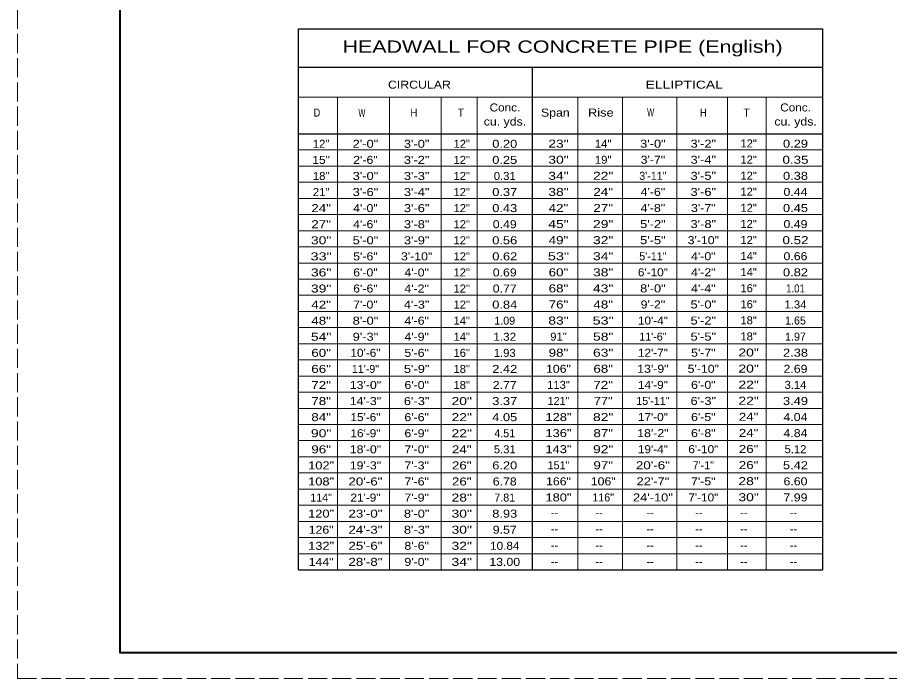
# Model space of a CAD drawing. Extents: x 685.4 to 719.4, y 1059.8 to 1105.8.
# Drawn here: x 685.44 to 702.44, y 1059.77 to 1072.65 of the extents above; entities that cross this region are included whole.
import ezdxf
from ezdxf.enums import TextEntityAlignment as Align

# ---------------------------------------------------------------- set-up
doc = ezdxf.new("R2010")
doc.units = 0
doc.header["$LTSCALE"] = 0.062
doc.linetypes.add('LONG_DASHED', pattern=[7.5, 6, -1.5])
doc.layers.add('1', color=7, linetype='Continuous', lineweight=13)

msp = doc.modelspace()

# ---------------------------------------------------------------- linework, layer by layer
at = {"layer": '1', "lineweight": 25}
for p, q in [((690.91875, 1061.88917), (690.91875, 1072.433)), ((690.91875, 1072.433), (701.14175, 1072.433)), ((701.14175, 1061.88917), (701.14175, 1072.433)), ((690.91875, 1071.68142), (701.14175, 1071.68142)), ((695.4815, 1061.88917), (695.4815, 1071.68142)), ((690.91875, 1070.38517), (701.14175, 1070.38517)), ((690.91875, 1061.88917), (701.14175, 1061.88917))]:
    msp.add_line(p, q, dxfattribs=at)
at = {"layer": '1'}
for p, q in [((690.91875, 1071.10025), (701.14175, 1071.10025)), ((691.6805, 1061.88917), (691.6805, 1071.10025)), ((692.69092, 1061.88917), (692.69092, 1071.10025)), ((693.70033, 1061.88917), (693.70033, 1071.10025)), ((694.40242, 1061.88917), (694.40242, 1071.10025)), ((696.36608, 1061.88917), (696.36608, 1071.10025)), ((697.23733, 1061.88917), (697.23733, 1071.10025)), ((698.29567, 1061.88917), (698.29567, 1071.10025)), ((699.2805, 1061.88917), (699.2805, 1071.10025)), ((700.03325, 1061.88917), (700.03325, 1071.10025)), ((690.91875, 1070.0705), (701.14175, 1070.0705)), ((690.91875, 1069.75583), (701.14175, 1069.75583)), ((690.91875, 1069.44117), (701.14175, 1069.44117)), ((690.91875, 1069.1265), (701.14175, 1069.1265)), ((690.91875, 1068.81183), (701.14175, 1068.81183)), ((690.91875, 1068.49717), (701.14175, 1068.49717)), ((690.91875, 1068.1825), (701.14175, 1068.1825)), ((690.91875, 1067.86783), (701.14175, 1067.86783)), ((690.91875, 1067.55317), (701.14175, 1067.55317)), ((690.91875, 1067.2385), (701.14175, 1067.2385)), ((690.91875, 1066.92383), (701.14175, 1066.92383)), ((690.91875, 1066.60917), (701.14175, 1066.60917)), ((690.91875, 1066.2945), (701.14175, 1066.2945)), ((690.91875, 1065.97983), (701.14175, 1065.97983)), ((690.91875, 1065.66517), (701.14175, 1065.66517)), ((690.91875, 1065.3505), (701.14175, 1065.3505)), ((690.91875, 1065.03583), (701.14175, 1065.03583)), ((690.91875, 1064.72117), (701.14175, 1064.72117)), ((690.91875, 1064.4065), (701.14175, 1064.4065)), ((690.91875, 1064.09183), (701.14175, 1064.09183)), ((690.91875, 1063.77717), (701.14175, 1063.77717)), ((690.91875, 1063.4625), (701.14175, 1063.4625)), ((690.91875, 1063.14783), (701.14175, 1063.14783)), ((690.91875, 1062.83317), (701.14175, 1062.83317)), ((690.91875, 1062.5185), (701.14175, 1062.5185)), ((690.91875, 1062.20383), (701.14175, 1062.20383))]:
    msp.add_line(p, q, dxfattribs=at)
at = {"layer": '1', "linetype": 'LONG_DASHED'}
msp.add_lwpolyline([(685.44108, 1059.77067), (719.44108, 1059.77067), (719.44108, 1081.77067), (685.44108, 1081.77067)], close=True, dxfattribs=at)
at = {"layer": '1', "lineweight": 25}
msp.add_lwpolyline([(718.94108, 1060.27067), (687.44108, 1060.27067), (687.44108, 1081.27067)], dxfattribs=at)
at = {"layer": '1', "lineweight": 40}
msp.add_lwpolyline([(687.44108, 1081.27067), (718.94108, 1081.27067), (718.94108, 1060.27067), (687.44108, 1060.27067)], close=True, dxfattribs=at)

# ---------------------------------------------------------------- texts
at = {"layer": '1'}
for s, height, width, p in [('HEADWALL FOR CONCRETE PIPE (English)', 0.24, 1.3, (691.77833, 1071.96442)), ('CIRCULAR', 0.156, 1.15, (692.66392, 1071.2655)), ('ELLIPTICAL', 0.156, 1.3, (697.68483, 1071.2655)), ('D', 0.156, 0.85, (691.216, 1070.72058)), ('W', 0.156, 0.7, (692.08658, 1070.71608)), ('H', 0.156, 0.9, (693.10075, 1070.72275)), ('Span', 0.156, 1.15, (695.646, 1070.72058)), ('Rise', 0.156, 1.2, (696.5625, 1070.72108)), ('W', 0.156, 0.7, (697.71475, 1070.72442)), ('H', 0.156, 0.9, (698.74292, 1070.72108))]:
    msp.add_text(s, height=height, dxfattribs=dict(at, width=width)).set_placement(p)
for s, height, p in [('T', 0.156, (694.0215, 1070.72108)), ('T', 0.156, (699.59017, 1070.72275)), ('--', 0.16, (695.841, 1062.922)), ('--', 0.16, (696.70675, 1062.922)), ('--', 0.16, (697.70033, 1062.922)), ('--', 0.16, (698.65133, 1062.922)), ('--', 0.16, (699.53133, 1062.922)), ('--', 0.16, (700.4965, 1062.922)), ('--', 0.16, (695.841, 1062.60467)), ('--', 0.16, (696.70675, 1062.60467)), ('--', 0.16, (697.70033, 1062.60467)), ('--', 0.16, (698.65133, 1062.60467)), ('--', 0.16, (699.53133, 1062.60467)), ('--', 0.16, (700.4965, 1062.60467)), ('--', 0.16, (695.841, 1062.28733)), ('--', 0.16, (696.70675, 1062.28733)), ('--', 0.16, (697.70033, 1062.28733)), ('--', 0.16, (698.65133, 1062.28733)), ('--', 0.16, (699.53133, 1062.28733)), ('--', 0.16, (700.4965, 1062.28733)), ('--', 0.16, (695.841, 1061.97)), ('--', 0.16, (696.70675, 1061.97)), ('--', 0.16, (697.70033, 1061.97)), ('--', 0.16, (698.65133, 1061.97)), ('--', 0.16, (699.53133, 1061.97)), ('--', 0.16, (700.4965, 1061.97))]:
    msp.add_text(s, height=height, dxfattribs=at).set_placement(p)
for s, width, p in [('Conc.', 1.1, (694.94429, 1070.821)), ('Conc.', 1.1, (700.60904, 1070.821)), ('cu. yds.', 1.15, (694.94437, 1070.547)), ('cu. yds.', 1.15, (700.60912, 1070.547)), ('12"', 1.05, (691.36083, 1070.11283)), ('2\'-0"', 1.2, (692.22471, 1070.11308)), ('3\'-0"', 1.2, (693.22296, 1070.11283)), ('12"', 1.05, (694.10125, 1070.11283)), ('0.20', 1.2, (694.93975, 1070.11283)), ('23"', 1.3, (695.98717, 1070.1155)), ('14"', 1.05, (696.85917, 1070.1155)), ('3\'-0"', 1.2, (697.82804, 1070.1155)), ('3\'-2"', 1.2, (698.81062, 1070.1155)), ('12"', 1.05, (699.69358, 1070.11958)), ('0.29', 1.2, (700.60737, 1070.1155)), ('15"', 1.1, (691.36087, 1069.7995)), ('2\'-6"', 1.15, (692.22475, 1069.79975)), ('3\'-2"', 1.2, (693.22296, 1069.7995)), ('12"', 1.05, (694.10125, 1069.7995)), ('0.25', 1.2, (694.93971, 1069.7995)), ('30"', 1.3, (695.98717, 1069.80217)), ('19"', 1.05, (696.85921, 1069.80217)), ('3\'-7"', 1.15, (697.82796, 1069.80217)), ('3\'-4"', 1.2, (698.81058, 1069.80217)), ('12"', 1.05, (699.69358, 1069.80625)), ('0.35', 1.25, (700.60737, 1069.80217)), ('18"', 1.05, (691.36083, 1069.48617)), ('3\'-0"', 1.2, (692.22479, 1069.48642)), ('3\'-3"', 1.2, (693.22287, 1069.48617)), ('12"', 1.05, (694.10125, 1069.48617)), ('0.31', 1.05, (694.93971, 1069.48617)), ('34"', 1.3, (695.98717, 1069.48883)), ('22"', 1.3, (696.85917, 1069.48883)), ('3\'-5"', 1.2, (698.81054, 1069.48883)), ('12"', 1.05, (699.69358, 1069.49292)), ('0.38', 1.2, (700.60733, 1069.48883)), ('21"', 1.05, (691.36083, 1069.17283)), ('3\'-6"', 1.2, (692.22475, 1069.17308)), ('3\'-4"', 1.2, (693.22292, 1069.17283)), ('12"', 1.05, (694.10125, 1069.17283)), ('0.37', 1.2, (694.93975, 1069.17283)), ('38"', 1.3, (695.98717, 1069.1755)), ('24"', 1.25, (696.85917, 1069.1755)), ('4\'-6"', 1.15, (697.828, 1069.1755)), ('3\'-6"', 1.2, (698.81058, 1069.1755)), ('12"', 1.05, (699.69358, 1069.17958)), ('0.44', 1.15, (700.60733, 1069.1755)), ('24"', 1.25, (691.36083, 1068.8595)), ('4\'-0"', 1.15, (692.22475, 1068.85975)), ('3\'-6"', 1.2, (693.22292, 1068.8595)), ('12"', 1.05, (694.10125, 1068.8595)), ('0.43', 1.2, (694.93975, 1068.8595)), ('42"', 1.25, (695.98717, 1068.86217)), ('27"', 1.25, (696.85917, 1068.86217)), ('4\'-8"', 1.15, (697.828, 1068.86217)), ('3\'-7"', 1.15, (698.81054, 1068.86217)), ('12"', 1.05, (699.69358, 1068.86625)), ('0.45', 1.2, (700.60733, 1068.86217)), ('27"', 1.25, (691.36083, 1068.54617)), ('4\'-6"', 1.15, (692.22475, 1068.54642)), ('3\'-8"', 1.2, (693.22292, 1068.54617)), ('12"', 1.05, (694.10125, 1068.54617)), ('0.49', 1.15, (694.93971, 1068.54617)), ('45"', 1.3, (695.98717, 1068.54883)), ('29"', 1.3, (696.85921, 1068.54883)), ('5\'-2"', 1.2, (697.82804, 1068.54883)), ('3\'-8"', 1.2, (698.81058, 1068.54883)), ('12"', 1.05, (699.69358, 1068.55292)), ('0.49', 1.15, (700.60729, 1068.54883)), ('30"', 1.3, (691.36083, 1068.23283)), ('5\'-0"', 1.2, (692.22479, 1068.23308)), ('3\'-9"', 1.2, (693.22292, 1068.23283)), ('12"', 1.05, (694.10125, 1068.23283)), ('0.56', 1.2, (694.93975, 1068.23283)), ('49"', 1.25, (695.98712, 1068.2355)), ('32"', 1.3, (696.85917, 1068.2355)), ('5\'-5"', 1.2, (697.828, 1068.2355)), ('3\'-10"', 1.15, (698.81062, 1068.2355)), ('12"', 1.05, (699.69358, 1068.23958)), ('0.52', 1.25, (700.60733, 1068.2355)), ('33"', 1.35, (691.36083, 1067.9195)), ('5\'-6"', 1.15, (692.22471, 1067.91975)), ('3\'-10"', 1.15, (693.22296, 1067.9195)), ('12"', 1.05, (694.10125, 1067.9195)), ('0.62', 1.2, (694.93979, 1067.9195)), ('53"', 1.35, (695.98712, 1067.92217)), ('34"', 1.3, (696.85917, 1067.92217)), ('4\'-0"', 1.15, (698.81058, 1067.92217)), ('14"', 1.05, (699.69358, 1067.92625)), ('0.66', 1.15, (700.60733, 1067.92217)), ('36"', 1.3, (691.36083, 1067.60617)), ('6\'-0"', 1.15, (692.22475, 1067.60642)), ('4\'-0"', 1.15, (693.22292, 1067.60617)), ('12"', 1.05, (694.10125, 1067.60617)), ('0.69', 1.15, (694.93971, 1067.60617)), ('60"', 1.25, (695.98717, 1067.60883)), ('38"', 1.3, (696.85917, 1067.60883)), ('6\'-10"', 1.1, (697.828, 1067.60883)), ('4\'-2"', 1.15, (698.81058, 1067.60883)), ('14"', 1.05, (699.69358, 1067.61292)), ('0.82', 1.2, (700.60737, 1067.60883)), ('39"', 1.3, (691.36079, 1067.29283)), ('6\'-6"', 1.15, (692.22475, 1067.29308)), ('4\'-2"', 1.15, (693.22292, 1067.29283)), ('12"', 1.05, (694.10125, 1067.29283)), ('0.77', 1.15, (694.93979, 1067.29283)), ('68"', 1.25, (695.98721, 1067.2955)), ('43"', 1.3, (696.85917, 1067.2955)), ('8\'-0"', 1.2, (697.828, 1067.2955)), ('4\'-4"', 1.15, (698.81058, 1067.2955)), ('16"', 1.05, (699.69358, 1067.29958)), ('1.01', 0.9, (700.60737, 1067.2955)), ('42"', 1.25, (691.36083, 1066.9795)), ('7\'-0"', 1.15, (692.22479, 1066.97975)), ('4\'-3"', 1.2, (693.22292, 1066.9795)), ('12"', 1.05, (694.10125, 1066.9795)), ('0.84', 1.2, (694.93971, 1066.9795)), ('76"', 1.25, (695.98717, 1066.98217)), ('48"', 1.25, (696.85921, 1066.98217)), ('9\'-2"', 1.15, (697.828, 1066.98217)), ('5\'-0"', 1.2, (698.81062, 1066.98217)), ('16"', 1.05, (699.69358, 1066.98625)), ('1.34', 1.05, (700.60733, 1066.98217)), ('48"', 1.25, (691.36087, 1066.66617)), ('8\'-0"', 1.2, (692.22475, 1066.66642)), ('4\'-6"', 1.15, (693.22292, 1066.66617)), ('14"', 1.05, (694.10125, 1066.66617)), ('83"', 1.3, (695.98717, 1066.66883)), ('53"', 1.35, (696.85912, 1066.66883)), ('10\'-4"', 1.1, (697.828, 1066.66883)), ('5\'-2"', 1.2, (698.81062, 1066.66883)), ('18"', 1.05, (699.69358, 1066.67292)), ('54"', 1.3, (691.36083, 1066.35283)), ('9\'-3"', 1.2, (692.22475, 1066.35308)), ('4\'-9"', 1.15, (693.22287, 1066.35283)), ('14"', 1.05, (694.10125, 1066.35283)), ('1.32', 1.1, (694.93975, 1066.35283)), ('91"', 1.05, (695.98721, 1066.3555)), ('58"', 1.3, (696.85917, 1066.3555)), ('5\'-5"', 1.2, (698.81058, 1066.3555)), ('18"', 1.05, (699.69358, 1066.35958)), ('60"', 1.25, (691.36083, 1066.0395)), ('10\'-6"', 1.1, (692.22475, 1066.03975)), ('5\'-6"', 1.15, (693.22287, 1066.0395)), ('16"', 1.05, (694.10125, 1066.0395)), ('1.93', 1.05, (694.93979, 1066.0395)), ('98"', 1.25, (695.98712, 1066.04217)), ('63"', 1.3, (696.85917, 1066.04217)), ('12\'-7"', 1.1, (697.82804, 1066.04217)), ('5\'-7"', 1.15, (698.81054, 1066.04217)), ('20"', 1.3, (699.69358, 1066.04625)), ('2.38', 1.2, (700.60733, 1066.04217)), ('66"', 1.25, (691.36083, 1065.72617)), ('5\'-9"', 1.2, (693.22292, 1065.72617)), ('18"', 1.05, (694.10125, 1065.72617)), ('2.42', 1.2, (694.93979, 1065.72617)), ('106"', 1.15, (695.98717, 1065.72883)), ('68"', 1.25, (696.85921, 1065.72883)), ('13\'-9"', 1.15, (697.82796, 1065.72883)), ('5\'-10"', 1.15, (698.81062, 1065.72883)), ('20"', 1.3, (699.69358, 1065.73292)), ('2.69', 1.15, (700.60729, 1065.72883)), ('72"', 1.25, (691.36083, 1065.41283)), ('13\'-0"', 1.15, (692.22479, 1065.41308)), ('6\'-0"', 1.15, (693.22292, 1065.41283)), ('18"', 1.05, (694.10125, 1065.41283)), ('2.77', 1.15, (694.93979, 1065.41283)), ('113"', 1.05, (695.98717, 1065.4155)), ('72"', 1.25, (696.85917, 1065.4155)), ('14\'-9"', 1.1, (697.82796, 1065.4155)), ('6\'-0"', 1.15, (698.81058, 1065.4155)), ('22"', 1.3, (699.69358, 1065.41958)), ('3.14', 1.05, (700.60733, 1065.4155)), ('78"', 1.25, (691.36083, 1065.0995)), ('14\'-3"', 1.15, (692.22475, 1065.09975)), ('6\'-3"', 1.2, (693.22292, 1065.0995)), ('20"', 1.3, (694.10125, 1065.0995)), ('3.37', 1.2, (694.93971, 1065.0995)), ('77"', 1.2, (696.85912, 1065.10217)), ('6\'-3"', 1.2, (698.81058, 1065.10217)), ('22"', 1.3, (699.69358, 1065.10625)), ('3.49', 1.2, (700.60737, 1065.10217)), ('84"', 1.25, (691.36087, 1064.78617)), ('15\'-6"', 1.1, (692.22471, 1064.78642)), ('6\'-6"', 1.15, (693.22292, 1064.78617)), ('22"', 1.3, (694.10125, 1064.78617)), ('4.05', 1.2, (694.93975, 1064.78617)), ('128"', 1.2, (695.98712, 1064.78883)), ('82"', 1.3, (696.85917, 1064.78883)), ('17\'-0"', 1.1, (697.82804, 1064.78883)), ('6\'-5"', 1.15, (698.81054, 1064.78883)), ('24"', 1.25, (699.69358, 1064.79292)), ('4.04', 1.15, (700.60733, 1064.78883)), ('90"', 1.3, (691.36087, 1064.47283)), ('16\'-9"', 1.1, (692.22471, 1064.47308)), ('6\'-9"', 1.15, (693.22287, 1064.47283)), ('22"', 1.3, (694.10125, 1064.47283)), ('136"', 1.2, (695.98717, 1064.4755)), ('87"', 1.25, (696.85917, 1064.4755)), ('18\'-2"', 1.15, (697.828, 1064.4755)), ('6\'-8"', 1.15, (698.81058, 1064.4755)), ('24"', 1.25, (699.69358, 1064.47958)), ('4.84', 1.15, (700.60737, 1064.4755)), ('96"', 1.25, (691.36079, 1064.1595)), ('18\'-0"', 1.15, (692.22475, 1064.15975)), ('7\'-0"', 1.15, (693.22296, 1064.1595)), ('24"', 1.25, (694.10125, 1064.1595)), ('5.31', 1.05, (694.93979, 1064.1595)), ('143"', 1.2, (695.98717, 1064.16217)), ('92"', 1.3, (696.85921, 1064.16217)), ('19\'-4"', 1.1, (697.82796, 1064.16217)), ('6\'-10"', 1.1, (698.81058, 1064.16217)), ('26"', 1.25, (699.69358, 1064.16625)), ('5.12', 1.05, (700.60733, 1064.16217)), ('102"', 1.2, (691.36083, 1063.84617)), ('19\'-3"', 1.15, (692.22471, 1063.84642)), ('7\'-3"', 1.15, (693.22287, 1063.84617)), ('26"', 1.25, (694.10125, 1063.84617)), ('6.20', 1.2, (694.93975, 1063.84617)), ('97"', 1.25, (696.85912, 1063.84883)), ('20\'-6"', 1.25, (697.828, 1063.84883)), ('26"', 1.25, (699.69358, 1063.85292)), ('5.42', 1.2, (700.60729, 1063.84883)), ('108"', 1.2, (691.36079, 1063.53283)), ('20\'-6"', 1.25, (692.22475, 1063.53308)), ('7\'-6"', 1.15, (693.22287, 1063.53283)), ('26"', 1.25, (694.10125, 1063.53283)), ('6.78', 1.15, (694.93975, 1063.53283)), ('166"', 1.15, (695.98721, 1063.5355)), ('106"', 1.15, (696.85917, 1063.5355)), ('22\'-7"', 1.2, (697.828, 1063.5355)), ('7\'-5"', 1.15, (698.81054, 1063.5355)), ('28"', 1.3, (699.69358, 1063.53958)), ('6.60', 1.15, (700.60733, 1063.5355)), ('21\'-9"', 1.1, (692.22479, 1063.21975)), ('7\'-9"', 1.15, (693.22292, 1063.2195)), ('28"', 1.3, (694.10125, 1063.2195)), ('180"', 1.2, (695.98712, 1063.22217)), ('24\'-10"', 1.2, (697.828, 1063.22217)), ('7\'-10"', 1.1, (698.81062, 1063.22217)), ('30"', 1.3, (699.69358, 1063.22625)), ('7.99', 1.15, (700.60733, 1063.22217)), ('120"', 1.2, (691.36083, 1062.90617)), ('23\'-0"', 1.25, (692.22475, 1062.90642)), ('8\'-0"', 1.2, (693.22292, 1062.90617)), ('30"', 1.3, (694.10125, 1062.90617)), ('8.93', 1.2, (694.93971, 1062.90617)), ('126"', 1.15, (691.36083, 1062.59283)), ('24\'-3"', 1.25, (692.22475, 1062.59308)), ('8\'-3"', 1.2, (693.22292, 1062.59283)), ('30"', 1.3, (694.10125, 1062.59283)), ('9.57', 1.15, (694.93975, 1062.59283)), ('132"', 1.2, (691.36083, 1062.2795)), ('25\'-6"', 1.25, (692.22475, 1062.27975)), ('8\'-6"', 1.15, (693.22292, 1062.2795)), ('32"', 1.3, (694.10125, 1062.2795)), ('10.84', 1.1, (694.93971, 1062.2795)), ('144"', 1.15, (691.36087, 1061.96617)), ('28\'-8"', 1.25, (692.22479, 1061.96642)), ('9\'-0"', 1.15, (693.22292, 1061.96617)), ('34"', 1.3, (694.10125, 1061.96617)), ('13.00', 1.15, (694.93975, 1061.96617))]:
    msp.add_text(s, height=0.156, dxfattribs=dict(at, width=width)).set_placement(p, align=Align.CENTER)
for s, p in [('3\'-11"', (697.82804, 1069.48883)), ('5\'-11"', (697.82804, 1067.92217)), ('1.09', (694.93979, 1066.66617)), ('1.65', (700.60737, 1066.66883)), ('11\'-6"', (697.828, 1066.3555)), ('1.97', (700.60733, 1066.3555)), ('11\'-9"', (692.22475, 1065.72642)), ('121"', (695.98717, 1065.10217)), ('15\'-11"', (697.82804, 1065.10217)), ('4.51', (694.93979, 1064.47283)), ('151"', (695.98721, 1063.84883)), ('7\'-1"', (698.81062, 1063.84883)), ('114"', (691.36083, 1063.2195)), ('7.81', (694.93975, 1063.2195)), ('116"', (696.85917, 1063.22217))]:
    msp.add_text(s, height=0.156, dxfattribs=at).set_placement(p, align=Align.CENTER)

doc.saveas('drawing.dxf')
